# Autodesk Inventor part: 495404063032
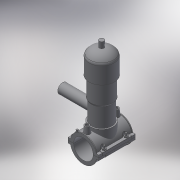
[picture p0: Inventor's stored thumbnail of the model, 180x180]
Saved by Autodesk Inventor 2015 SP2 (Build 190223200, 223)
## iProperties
Created: 2017-07
Part Number: 495404063032
Material: Generic
Description: PLASSON TAPPING VALVE 63-32
Document SubType Name: Modeling
Designer: KIM
Density: 1 g/cm^3
Appearance: Default
Author: KIM
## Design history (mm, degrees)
derived "495404-4954S4.ipt"
feature "Solid1::495404-4954S4.ipt"
feature "Solid2::495404-4954S4.ipt"
tag "TaggingFeature1"
body "Solid1"
body "Solid2"
other parameters: "d_" = 63, "B_" = 99, "H_" = 126, "L_" = 118, "d_t" = 6, "d_1" = 32, "H_1" = 46, "H_2" = 244, "d148" = 0.945, "d160" = 0.945, "d169" = 3, "d192" = 6.8, "d228" = 25.6, "d0" = 63, "d2" = 99, "d3" = 15.75, "d4" = 118, "d5" = 0, "d6" = 0.1, "d8" = 0, "d19" = 6, "d20" = 6, "d21" = 70.8, "d23" = 0, "d24" = 35.4, "d26" = 0, "d27" = 3, "d28" = 3, "d29" = 3, "d30" = 21, "d31" = 6, "d32" = 0, "d33" = 0, "d34" = 0.6, "d40" = 42.588, "d47" = 86.95, "d70" = 15, "d72" = 0, "d73" = 6, "d75" = 5, "d76" = 0, "d77" = 3.15, "d78" = 61.5, "d79" = 15, "d80" = 47.2, "d82" = 5 deg, "d84" = 4, "d85" = 14, "d86" = 0, "d87" = 3, "d88" = 0, "d89" = 1, "d90" = 1, "d91" = 94.4, "d92" = 0, "d93" = 0.5, "d94" = 33.15789, "d96" = 84.357, "d97" = 2.36, "d98" = 0, "d120" = 140 deg, "d121" = 24.228, "d122" = 20 deg, "d123" = 163.8, "d124" = 49.14, "d126" = 0, "d143" = 64.89, "d145" = 14.53846, "d149" = 0.945, "d150" = 15.99231, "d153" = 118, "d154" = 0, "d156" = 40.95, "d157" = 160 deg, "d159" = 3.78, "d161" = 0.945, "d162" = 70.8, "d163" = 0, "d164" = 31.5, "d167" = 6.3, "d168" = 39.95122, "d170" = 3, "d172" = 0, "d173" = 1, "d175" = 31.5, "d176" = 20 deg, "d177" = 4.41, "d178" = 18.9, "d180" = 0, "d183" = 7.56, "d184" = 3.528, "d185" = 38.35, "d186" = 38.35, "d187" = 40.95, "d188" = 5.67, "d189" = 4.41, "d190" = 0, "d191" = 61.425, "d193" = 6.8, "d194" = 2.95, "d195" = 90 deg, "d197" = 0, "d199" = 0, "d205" = 14.64, "d206" = 81.33333, "d207" = 244, "d208" = 224.48, "d209" = 207.4, "d210" = 200.08, "d211" = 146.4, "d212" = 85.4, "d213" = 65.88, "d214" = 73.2, "d216" = 19.52, "d217" = 70.76, "d218" = 80.52, "d220" = 63, "d222" = 0, "d223" = 81.9, "d224" = 126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
